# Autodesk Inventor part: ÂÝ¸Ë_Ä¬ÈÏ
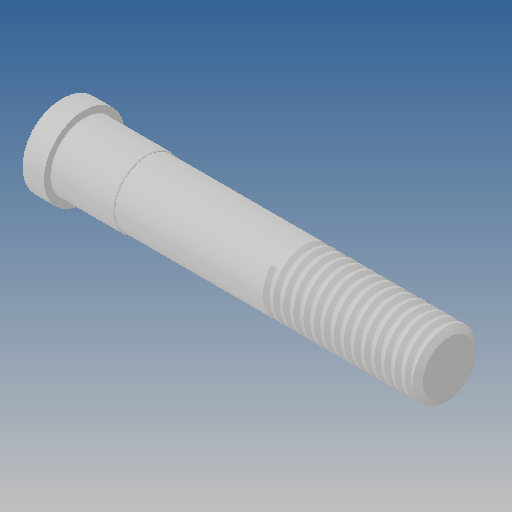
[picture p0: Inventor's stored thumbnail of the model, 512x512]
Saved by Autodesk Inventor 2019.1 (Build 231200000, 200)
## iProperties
Created: 2012-10
Part Number: ÂÝ¸Ë_Ä¬ÈÏ
Material: Ogólny
Document SubType Name: Modeling
Designer: CADENGINEERING4
Density: 1 g/cm^3
Appearance: Domyślna
Author: CADENGINEERING4
Revision Number: ÈÎºÎ
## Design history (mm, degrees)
feature "NONE"
node "Bryła1"
